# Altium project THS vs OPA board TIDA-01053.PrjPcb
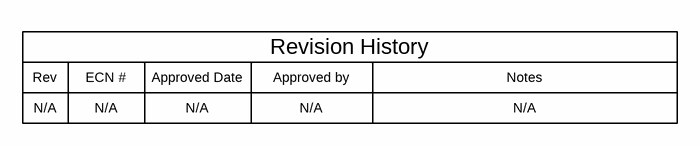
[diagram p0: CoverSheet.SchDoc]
CopyrightYear: 2017; PCB_Layout: Eric Beljaars; PCB_Rev: E1; PRJ_Customer: Public Release; PRJ_Engineer: Taras Dudar; PRJ_Number: TIDA-01053; PRJ_Title: ADC Driver; SCH_Rev: E1; TechSupport: http://www.ti.com/support; TID: 01053
3 sheets, 90 parts. Net scope: global (net labels, ports and power ports of the same name join across sheets).
Board file: PCB.PcbDoc
Sheets:
  CoverSheet.SchDoc
  OPA625_VCA_Disto_Hardware.SchDoc
  THS4551_VCA_Disto_Hardware.SchDoc

## Sheet CoverSheet.SchDoc
size 431 x 279 mm; Date: Not shown in title block; ApprovedBy: Not shown in title block; CheckedBy: Not shown in title block; Author: Not shown in title block; CompanyName: Not shown in title block; Engineer: Not shown in title block; Organization: Not shown in title block; Address1: Not shown in title block; Address2: Not shown in title block; Address3: Not shown in title block; Address4: Not shown in title block; DocumentNumber: 1; Revision: Use project parameter SCH_Rev; SheetNumber: 1; SheetTotal: 3; PageSetup: Record=PageOptions¦CenterHorizontal=True¦CenterVertical=True¦PrintScale=1.00¦XCorrection=1.00¦YCorrection=1.00¦PrintKind=0¦BorderSize=5000000¦LeftOffset=0¦BottomOffset=0¦Orientation=2¦PaperLength=1000¦PaperWidth=1000¦Scale=100¦PaperSource=15¦PrintQuality=600¦MediaType=1¦DitherType=10¦PaperKind=Letter¦PrintScaleMode=1

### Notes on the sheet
- Rev
- N/A
- ECN #
- Approved Date
- Approved by
- Revision History
- Notes

## Sheet OPA625_VCA_Disto_Hardware.SchDoc
size 431 x 279 mm; Date: Not shown in title block; ApprovedBy: Not shown in title block; CheckedBy: Not shown in title block; Author: Not shown in title block; CompanyName: Not shown in title block; Engineer: Not shown in title block; Organization: Not shown in title block; Address1: Not shown in title block; Address2: Not shown in title block; Address3: Not shown in title block; Address4: Not shown in title block; DocumentNumber: 1; Revision: Use project parameter SCH_Rev; SheetNumber: 2; SheetTotal: 3; PageSetup: Record=PageOptions¦CenterHorizontal=True¦CenterVertical=True¦PrintScale=1.00¦XCorrection=1.00¦YCorrection=1.00¦PrintKind=0¦BorderSize=5000000¦LeftOffset=0¦BottomOffset=0¦Orientation=2¦PaperLength=1000¦PaperWidth=1000¦Scale=100¦PaperSource=15¦PrintQuality=600¦MediaType=1¦DitherType=10¦PaperKind=Letter¦PrintScaleMode=1
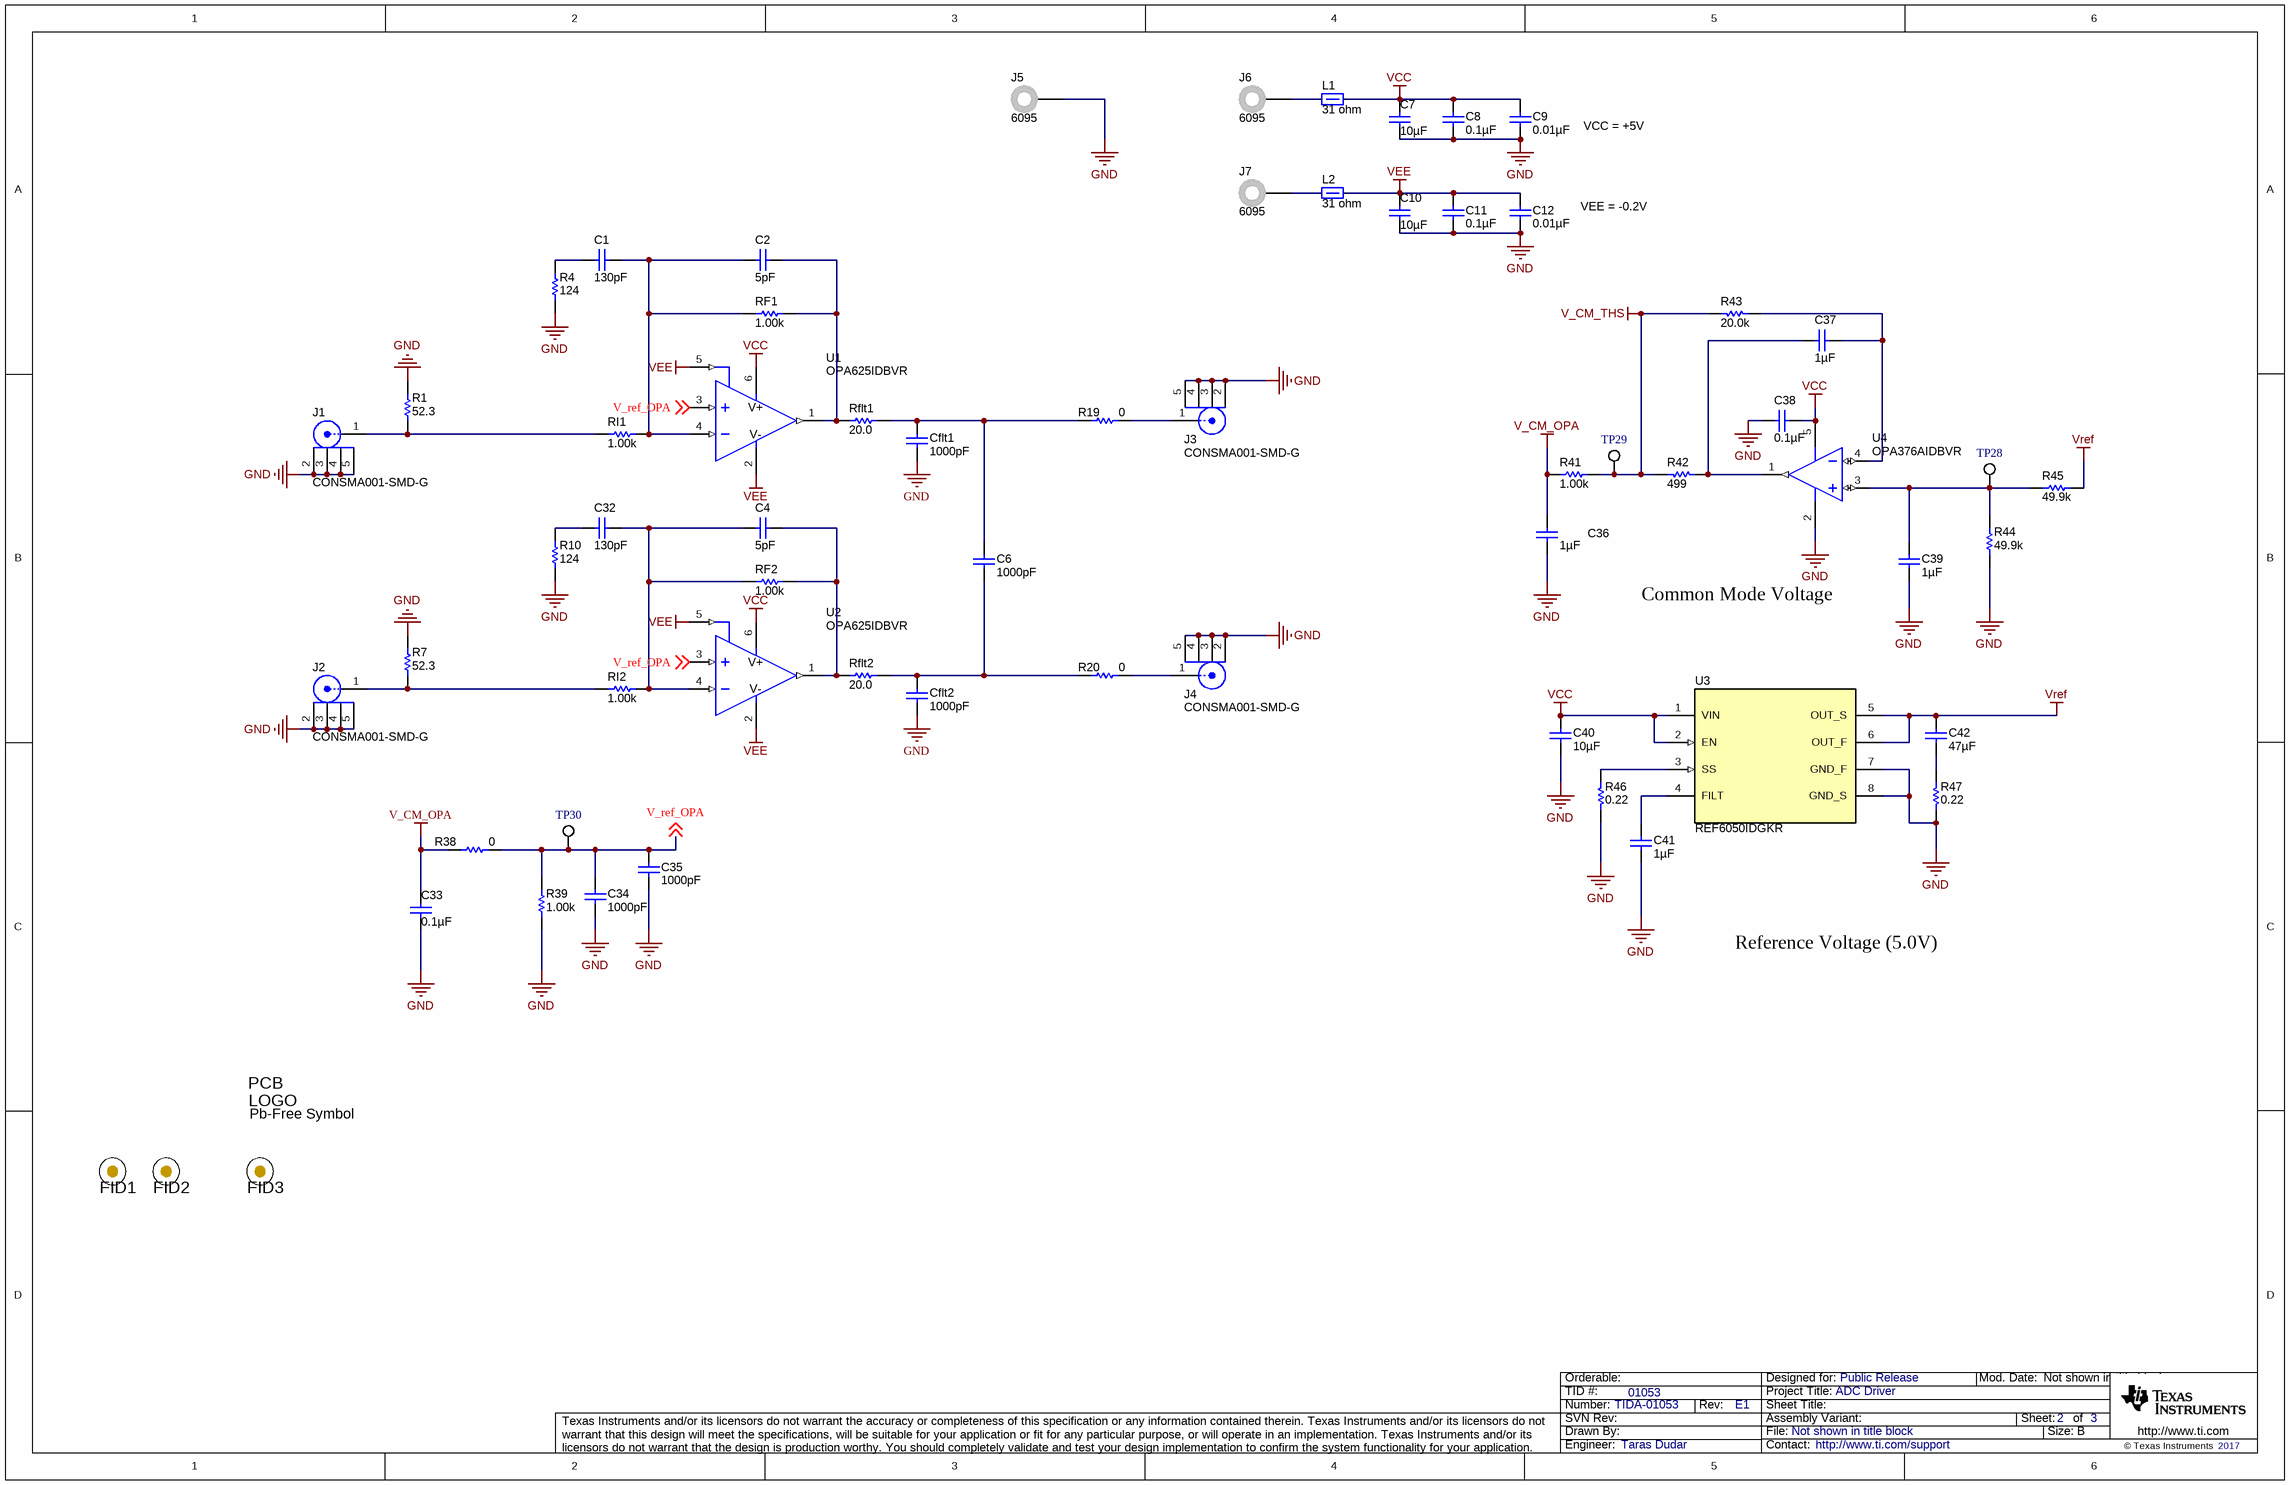
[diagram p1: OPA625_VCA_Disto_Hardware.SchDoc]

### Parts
C1  ValueDisplayed: 130pF  [0603]  (hidden comment: GRM1885C2A131JA01D)
C2  ValueDisplayed: 5pF  [0603]  (hidden comment: GRM1885C2A5R0CA01D)
C4  ValueDisplayed: 5pF  [0603]  (hidden comment: GRM1885C2A5R0CA01D)
C6  ValueDisplayed: 1000pF  [0603]  (hidden comment: C1608C0G2A102J080AA)
C7  ValueDisplayed: 10µF  [1210_280]  (hidden comment: UMK325AB7106KM-T)
C8  ValueDisplayed: 0.1µF  [0603]  (hidden comment: GRM188R72A104KA35D)
C9  ValueDisplayed: 0.01µF  [0603]  (hidden comment: GRM188R71E103KA01D)
C10  ValueDisplayed: 10µF  [1210_280]  (hidden comment: UMK325AB7106KM-T)
C11  ValueDisplayed: 0.1µF  [0603]  (hidden comment: GRM188R72A104KA35D)
C12  ValueDisplayed: 0.01µF  [0603]  (hidden comment: GRM188R71E103KA01D)
C32  ValueDisplayed: 130pF  [0603]  (hidden comment: GRM1885C2A131JA01D)
C33  ValueDisplayed: 0.1µF  [0603]  (hidden comment: C0603C104J3RACTU)
C34  ValueDisplayed: 1000pF  [0603]  (hidden comment: C0603C102J5GAC)
C35  ValueDisplayed: 1000pF  [0603]  (hidden comment: C0603C102J5GAC)
C36  ValueDisplayed: 1µF  [0603]  (hidden comment: GRM188R71E105KA12D)
C37  ValueDisplayed: 1µF  [0603]  (hidden comment: GRM188R71E105KA12D)
C38  ValueDisplayed: 0.1µF  [0603]  (hidden comment: C0603C104J3RACTU)
C39  ValueDisplayed: 1µF  [0603]  (hidden comment: GRM188R71E105KA12D)
C40  ValueDisplayed: 10µF  [0805]  (hidden comment: GRM21BR71A106KE51L)
C41  ValueDisplayed: 1µF  [0603]  (hidden comment: GRM188R71A105KA61D)
C42  ValueDisplayed: 47µF  [1210_270]  (hidden comment: GRM32ER71A476KE15L)
Cflt1  ValueDisplayed: 1000pF  [0603]  (hidden comment: C1608C0G2A102J080AA)
Cflt2  ValueDisplayed: 1000pF  [0603]  (hidden comment: C1608C0G2A102J080AA)
FID1  Fiducial  [Fiducial10-20]  (value not drawn)
FID2  Fiducial  [Fiducial10-20]  (value not drawn)
FID3  Fiducial  [Fiducial10-20]  (value not drawn)
J1  CONSMA001-SMD-G  [Linx_CONSMA001-SMD-G]
J2  CONSMA001-SMD-G  [Linx_CONSMA001-SMD-G]
J3  CONSMA001-SMD-G  [Linx_CONSMA001-SMD-G]
J4  CONSMA001-SMD-G  [Linx_CONSMA001-SMD-G]
J5  6095  [Keystone_6095]
J6  6095  [Keystone_6095]
J7  6095  [Keystone_6095]
L1  value 31 ohm  [1206]  (hidden comment: MI1206K310R-10)
L2  value 31 ohm  [1206]  (hidden comment: MI1206K310R-10)
Logo2  Pb-Free Symbol  [Pb-Free_Overlay_Small]  (no BOM)
R1  ValueDisplayed: 52.3  [0603]  (hidden comment: RC0603FR-0752R3L)
R4  ValueDisplayed: 124  [0603]  (hidden comment: RC0603FR-07124RL)
R7  ValueDisplayed: 52.3  [0603]  (hidden comment: RC0603FR-0752R3L)
R10  ValueDisplayed: 124  [0603]  (hidden comment: RC0603FR-07124RL)
R19  ValueDisplayed: 0  [0402]  (hidden comment: ERJ-2GE0R00X)
R20  ValueDisplayed: 0  [0402]  (hidden comment: ERJ-2GE0R00X)
R38  ValueDisplayed: 0  [0402]  (hidden comment: ERJ-2GE0R00X)
R39  ValueDisplayed: 1.00k  [0603]  (hidden comment: RT0603BRB071KL)
R41  ValueDisplayed: 1.00k  [0603]  (hidden comment: RT0603BRB071KL)
R42  ValueDisplayed: 499  [0603]  (hidden comment: RG1608P-4990-B-T5)
R43  ValueDisplayed: 20.0k  [0603]  (hidden comment: RG1608P-203-B-T5)
R44  ValueDisplayed: 49.9k  [0603]  (hidden comment: RG1608P-4992-B-T5)
R45  ValueDisplayed: 49.9k  [0603]  (hidden comment: RG1608P-4992-B-T5)
R46  value 0.22  [0603]  (hidden comment: ERJ-3RQFR22V)
R47  value 0.22  [0603]  (hidden comment: ERJ-3RQFR22V)
RF1  ValueDisplayed: 1.00k  [0603]  (hidden comment: RT0603BRB071KL)
RF2  ValueDisplayed: 1.00k  [0603]  (hidden comment: RT0603BRB071KL)
Rflt1  ValueDisplayed: 20.0  [0603]  (hidden comment: RT0603BRD0720RL)
Rflt2  ValueDisplayed: 20.0  [0603]  (hidden comment: RT0603BRD0720RL)
RI1  ValueDisplayed: 1.00k  [0603]  (hidden comment: RT0603BRB071KL)
RI2  ValueDisplayed: 1.00k  [0603]  (hidden comment: RT0603BRB071KL)
TP28  5015  [Testpoint_Keystone_Miniature]  (value not drawn)
TP29  5015  [Testpoint_Keystone_Miniature]  (value not drawn)
TP30  5015  [Testpoint_Keystone_Miniature]  (value not drawn)
U1  OPA625IDBVR  [DBV0006A_N]
U2  OPA625IDBVR  [DBV0006A_N]
U3  REF6050IDGKR  [DGK0008A_N]
U4  OPA376AIDBVR  [DBV0005A_N]

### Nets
GND: C7.2 C8.2 C9.2 C10.2 C11.2 C12.2 C33.2 C34.2 C35.2 C36.2 C38.1 C39.2 C40.1 C41.2 Cflt1.2 Cflt2.2 J1.2 J1.3 J1.4 J1.5 J2.2 J2.3 J2.4 J2.5 J3.2 J3.3 J3.4 J3.5 J4.2 J4.3 J4.4 J4.5 J5.1 R1.2 R4.1 R7.2 R10.1 R39.1 R44.1 R46.1 R47.2 U3.7(GND_F) U3.8(GND_S) U4.2(V-)
V_CM_OPA: C33.1 C36.1 R38.1 R41.1
V_CM_THS: R41.2 R42.2 R43.2 TP29.1
VCC: C7.1 C8.1 C9.1 C38.2 C40.2 L1.2 U1.6(V+) U2.6(V+) U3.1(VIN) U3.2(EN) U4.5(V+)
VEE: C10.1 C11.1 C12.1 L2.2 U1.2(V-) U1.5(MODE) U2.2(V-) U2.5(MODE)
Vref: C42.1 R45.2 U3.5(OUT_S) U3.6(OUT_F)
V_ref_OPA: C34.1 C35.1 R38.2 R39.2 TP30.1 U1.3(IN+) U2.3(IN+) ; off-sheet V_ref_OPA
NetC1_1: C1.1 R4.2
NetC1_2: C1.2 C2.2 RF1.1 RI1.2 U1.4(IN-)
NetC2_1: C2.1 RF1.2 Rflt1.1 U1.1(OUT)
NetC4_1: C4.1 RF2.2 Rflt2.1 U2.1(OUT)
NetC4_2: C4.2 C32.2 RF2.1 RI2.2 U2.4(IN-)
NetC6_1: C6.1 Cflt1.1 R19.1 Rflt1.2
NetC6_2: C6.2 Cflt2.1 R20.1 Rflt2.2
NetC32_1: C32.1 R10.2
NetC37_1: C37.1 R42.1 U4.1(OUT)
NetC37_2: C37.2 R43.1 U4.4(IN-)
NetC39_1: C39.1 R44.2 R45.1 TP28.1 U4.3(IN+)
NetC41_1: C41.1 U3.4(FILT)
NetC42_2: C42.2 R47.1
NetJ1_1: J1.1 R1.1 RI1.1
NetJ2_1: J2.1 R7.1 RI2.1
NetJ3_1: J3.1 R19.2
NetJ4_1: J4.1 R20.2
NetJ6_1: J6.1 L1.1
NetJ7_1: J7.1 L2.1
NetR46_2: R46.2 U3.3(SS)

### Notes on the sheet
- VCC = +5V
- VEE = -0.2V
- Common Mode Voltage
- Reference Voltage (5.0V)

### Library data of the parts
C1 C32 = GRM1885C2A131JA01D: CAP, CERM, 130 pF, 100 V, +/- 5%, C0G/NP0, 0603; Manufacturer: MuRata; Polarized: N; CompType: Capacitor; Value: 130pF; U/M: EA; Cap_F: 0.00000000013; Tolerance_%: 5; Value1: Unknown; VDC_V: 100; Value2: 100V; TaMin_C: -55; TaMax_C: 125; SizeArea_mm2: 1.28; SizeAreaWB_mm2: 4.68; SizeX_mm: 1.6; SizeY_mm: 0.8; SizeZ_mm: 1; AEC Category: Q200
C2 C4 = GRM1885C2A5R0CA01D: CAP, CERM, 5 pF, 100 V, +/- 5%, C0G/NP0, 0603; Manufacturer: MuRata; Polarized: N; CompType: Capacitor; Value: 5pF; U/M: EA; Cap_F: 0.000000000005; Tolerance_%: 5; Value1: Unknown; VDC_V: 100; Value2: 100V; TaMin_C: -55; TaMax_C: 125; SizeArea_mm2: 1.28; SizeAreaWB_mm2: 4.68; SizeX_mm: 1.6; SizeY_mm: 0.8; SizeZ_mm: 1; AEC Category: Q200
C6 Cflt1 Cflt2 = C1608C0G2A102J080AA: CAP, CERM, 1000 pF, 100 V, +/- 5%, C0G/NP0, 0603; Manufacturer: TDK; Polarized: N; CompType: Capacitor; Value: 1000pF; U/M: EA; Cap_F: 0.000000001; Tolerance_%: 5; ESR_ohm: 0.0589; Value1: 0.0589 ohm; VDC_V: 100; Value2: 100V; TaMin_C: -55; TaMax_C: 125; SizeArea_mm2: 1.28; SizeAreaWB_mm2: 4.68; SizeX_mm: 1.6; SizeY_mm: 0.8; SizeZ_mm: 1; AEC Category: Q200
C7 C10 = UMK325AB7106KM-T: CAP, CERM, 10 µF, 50 V, +/- 10%, X7R, 1210; Manufacturer: Taiyo Yuden; Polarized: N; CompType: Capacitor; Value: 10uF; U/M: EA; Cap_F: 0.00001; Tolerance_%: 10; Value1: Unknown; VDC_V: 50; Value2: 50V; TaMin_C: -55; TaMax_C: 125; Cap_Case: 1210; AEC Category: Q200
C8 C11 = GRM188R72A104KA35D: CAP, CERM, 0.1 µF, 100 V, +/- 10%, X7R, 0603; Manufacturer: MuRata; Polarized: N; CompType: Capacitor; Value: 0.1uF; U/M: EA; Cap_F: 0.0000001; Tolerance_%: 10; Value1: Unknown; VDC_V: 100; Value2: 100V; TaMin_C: -55; TaMax_C: 125; SizeArea_mm2: 1.28; SizeAreaWB_mm2: 4.68; SizeX_mm: 1.6; SizeY_mm: 0.8; SizeZ_mm: 1; AEC Category: Q200
C9 C12 = GRM188R71E103KA01D: CAP, CERM, 0.01 µF, 25 V, +/- 10%, X7R, 0603; Manufacturer: MuRata; Polarized: N; CompType: Capacitor; Value: 0.01uF; U/M: EA; Cap_F: 0.00000001; Tolerance_%: 10; Value1: Unknown; VDC_V: 25; Value2: 25V; TaMin_C: -55; TaMax_C: 125; SizeArea_mm2: 1.28; SizeAreaWB_mm2: 4.68; SizeX_mm: 1.6; SizeY_mm: 0.8; SizeZ_mm: 1; AEC Category: Q200
C33 = C0603C104J3RACTU: CAP, CERM, 0.1 µF, 25 V, +/- 5%, X7R, 0603; Manufacturer: Kemet; Polarized: N; CompType: Capacitor; Value: 0.1uF; U/M: EA; Cap_F: 0.0000001; Tolerance_%: 5; Value1: Unknown; VDC_V: 25; Value2: 25V; TaMin_C: -55; TaMax_C: 125
C34 C35 = C0603C102J5GAC: CAP, CERM, 1000 pF, 50 V, +/- 5%, C0G/NP0, 0603; Manufacturer: Kemet; Polarized: N; CompType: Capacitor; Value: 1000pF; U/M: EA; Cap_F: 0.000000001; Tolerance_%: 5; Value1: Unknown; VDC_V: 50; Value2: 50V; TaMin_C: -55; TaMax_C: 125; SizeArea_mm2: 1.28; SizeAreaWB_mm2: 4.68; SizeX_mm: 1.6; SizeY_mm: 0.8; SizeZ_mm: 1; AEC Category: Q200
C36 C37 C39 = GRM188R71E105KA12D: CAP, CERM, 1 µF, 25 V, +/- 10%, X7R, 0603; Manufacturer: MuRata; Polarized: N; CompType: Capacitor; Value: 1uF; U/M: EA; Cap_F: 0.000001; Tolerance_%: 10; Value1: Unknown; VDC_V: 25; Value2: 25V; TaMin_C: -55; TaMax_C: 125; AEC Category: Q200
C38 = C0603C104J3RACTU: CAP, CERM, 0.1 µF, 25 V, +/- 5%, X7R, 0603; Manufacturer: Kemet; Polarized: N; CompType: Capacitor; Value: 0.1uF; U/M: EA; Cap_F: 0.0000001; Tolerance_%: 5; Value1: Unknown; VDC_V: 25; Value2: 25V; TaMin_C: -55; TaMax_C: 125; AEC Category: Q200
C40 = GRM21BR71A106KE51L: CAP, CERM, 10uF, 10V, +/-10%, X7R, 0805; Manufacturer: MuRata; Polarized: N; CompType: Capacitor; U/M: EA; Cap_F: 0.00001; Tolerance_%: 10; ESR_Ohm: 0.003; Value1: 0.003 ohm; TaMin_C: -55; TaMax_C: 125
C41 = GRM188R71A105KA61D: CAP, CERM, 1uF, 10V, +/-10%, X7R, 0603; Manufacturer: MuRata; Polarized: N; CompType: Capacitor; U/M: EA; Cap_F: 0.000001; Tolerance_%: 10; ESR_Ohm: 0.011; Value1: 0.011 ohm; TaMin_C: -55; TaMax_C: 125
C42 = GRM32ER71A476KE15L: CAP, CERM, 47 µF, 10 V, +/- 10%, X7R, 1210; Manufacturer: MuRata; Polarized: N; CompType: Capacitor; Value: 47uF; U/M: EA; Cap_F: 0.000047; Tolerance_%: 10; Value1: Unknown; Value2: 10V; TaMin_C: -55; TaMax_C: 125; Cap_Case: 1210; SizeArea_mm2: 8; SizeAreaWB_mm2: 14.7; SizeX_mm: 3.2; SizeY_mm: 2.5; SizeZ_mm: 2.7; AEC Category: Q200
FID1-FID3 = Fiducial: Fiducial mark.  There is nothing to buy or mount.; SymbolCreator: codlsc
J1-J4 = CONSMA001-SMD-G: Jack, SMA, PCB, Gold, SMT; Manufacturer: Linx Technologies; SymbolCreator: X0208326
J5-J7 = 6095: Standard Banana Jack, Uninsulated; Manufacturer: Keystone; SymbolCreator: a0412235; CompType: Connector
L1 L2 = MI1206K310R-10: Ferrite Bead, 31 ohm @ 100 MHz, 1.5 A, 1206; Manufacturer: Laird-Signal Integrity Products; Imax_A: 1.5; DCR_ohm: 0.045; Value1: 0.045 ohm; Value2: 1.5A; ZTyp@100MHz_Ohm: 31; Ztyp@1GHz_Ohm: 41
Logo2 = Pb-Free: SymbolCreator: a0412235
R1 R7 = RC0603FR-0752R3L: RES, 52.3, 1%, 0.1 W, 0603; Manufacturer: Yageo America; CompType: Resistor; Value: 52.3; Value_Code: 52R3; Tolerance_%: 1; Power_W: 0.1; Value2: 0.1W; VDC_V: 150; TempCo: 200 ppm/C; SizeArea_mm2: 1.28; SizeX_mm: 1.6; SizeY_mm: 0.8; EIA_Code: E96; U/M: EA; AEC Category: Q200
R4 R10 = RC0603FR-07124RL: RES, 124, 1%, 0.1 W, 0603; Manufacturer: Yageo America; CompType: Resistor; Value: 124; Value_Code: 124R; Tolerance_%: 1; Power_W: 0.1; Value2: 0.1W; VDC_V: 150; TempCo: 200 ppm/C; SizeArea_mm2: 1.28; SizeX_mm: 1.6; SizeY_mm: 0.8; EIA_Code: E96; U/M: EA; AEC Category: Q200
R19 R20 R38 = ERJ-2GE0R00X: RES, 0, 5%, 0.063 W, 0402; Manufacturer: Panasonic; CompType: Resistor; Value: 0; Value_Code: 0000; Tolerance_%: 5; Power_W: 0.063; Value2: 0.063W; VDC_V: 50; TempCo: 600 ppm/C; EIA_Code: E24; U/M: EA; AEC Category: Q200
R39 R41 RF1 RF2 RI1 RI2 = RT0603BRB071KL: RES, 1.00 k, 0.1%, 0.1 W, 0603; Manufacturer: Yageo America; CompType: Resistor; Value: 1.00k; Res_ohm: 1000; Value_Code: 1k00; Tolerance_%: 0.1; Value2: 0.1W; VDC_V: 75; TempCo: 10 ppm/C; SizeArea_mm2: 1.28; SizeX_mm: 1.6; SizeY_mm: 0.8; SizeZ_mm: 1; EIA_Code: E192; U/M: EA; AEC Category: Q200; AEC Qualified: N
R42 = RG1608P-4990-B-T5: RES, 499, 0.1%, 0.1 W, 0603; Manufacturer: Susumu Co Ltd; CompType: Resistor; Value: 499; Value_Code: 499R; Tolerance_%: 0.1; Value2: 0.1W; VDC_V: 75; TempCo: 25 ppm/C; EIA_Code: E192; U/M: EA; AEC Category: Q200
R43 = RG1608P-203-B-T5: RES, 20.0 k, 0.1%, 0.1 W, 0603; Manufacturer: Susumu Co Ltd; CompType: Resistor; Value: 20.0k; Res_ohm: 20000; Value_Code: 20k0; Tolerance_%: 0.1; Value2: 0.1W; VDC_V: 75; TempCo: 25 ppm/C; EIA_Code: E192; U/M: EA; AEC Category: Q200
R44 R45 = RG1608P-4992-B-T5: RES, 49.9 k, 0.1%, 0.1 W, 0603; Manufacturer: Susumu Co Ltd; CompType: Resistor; Value: 49.9k; Res_ohm: 49900; Value_Code: 49k9; Tolerance_%: 0.1; Value2: 0.1W; VDC_V: 75; TempCo: 25 ppm/C; EIA_Code: E192; U/M: EA; AEC Category: Q200
R46 R47 = ERJ-3RQFR22V: RES, 0.22 ohm, 1%, 0.1W, 0603; Manufacturer: Panasonic; CompType: Resistor; Value_Code: R220; Tolerance_%: 1; Power_W: 0.1; TempCo: 300 ppm/C; EIA_Code: E96; U/M: EA
Rflt1 Rflt2 = RT0603BRD0720RL: RES, 20.0, 0.1%, 0.1 W, 0603; Manufacturer: Yageo America; CompType: Resistor; Value: 20.0; Res_ohm: 20; Value_Code: 20R0; Tolerance_%: 0.1; Value2: 0.1W; VDC_V: 75; TempCo: 25 ppm/C; SizeArea_mm2: 1.28; SizeX_mm: 1.6; SizeY_mm: 0.8; SizeZ_mm: 1; EIA_Code: E192; U/M: EA; AEC Category: Q200
TP28-TP30 = 5015: Test Point, Miniature, SMT; Manufacturer: Keystone; CompType: Test Point Loop
U1 U2 = OPA625IDBVR: High Bandwidth, High Precision, Low Noise and Distortion Amplifier with Ultra-Fast Transition time Low Power mode, DBV0006A (SOT-6); Alternate PartNumber: OPA625IDBVT; Manufacturer: Texas Instruments; SymbolCreator: Altium; SizeArea_mm2: 8.12; SizeAreaWB_mm2: 14.82; SizeX_mm: 2.8; SizeY_mm: 2.9; SizeZ_mm: 1.45; CompType: IC; U/M: EA
U3 = REF6050IDGKR: High-Precision Voltage Reference with Integrated High-Bandwidth Buffer, DGK0008A (VSSOP-8); Alternate PartNumber: REF6050IDGKT; Manufacturer: Texas Instruments; SymbolCreator: Altium; SizeArea_mm2: 15.655; SizeAreaWB_mm2: 35.955; SizeX_mm: 5.05; SizeY_mm: 3.1; SizeZ_mm: 1.1; CompType: IC; U/M: EA
U4 = OPA376AIDBVR: Precision, Low Noise, Low Iq Operational Amplifier, 2.2 to 5.5 V, -40 to 125 degC, 5-pin SOT23 (DBV0005A), Green (RoHS & no Sb/Br); Manufacturer: Texas Instruments; Alternate PartNumber: Equivalent; CMRR(Min)(dB): 76; IIB(Max)(pA): 10; Iq per channel(Max)(mA): 0.95; Number of Channels: 1; Offset Drift(Typ)(uV/C): 0.32; Slew Rate(Typ)(V/us): 2; Sub Family: Low Input Bias Current Amp (<=10pA), Low Noise Amp (<=10nV/rtHz), Low Offset Voltage Amplifier (<=500uV), Low Supply Voltage Amplifier (<=2.7V), Precision Amplifier; Total Supply Voltage(Max)(+5V is 5, +/-5V is 10): 5.5; Total Supply Voltage(Min)(+5V is 5, +/-5V is 10): 2.2; Vio (25C)(Max)(mV): 0.025; Vn at 1kHz(Typ)(nV/rtHz): 7.5

## Sheet THS4551_VCA_Disto_Hardware.SchDoc
size 431 x 279 mm; Date: Not shown in title block; ApprovedBy: Not shown in title block; CheckedBy: Not shown in title block; Author: Not shown in title block; CompanyName: Not shown in title block; Engineer: Not shown in title block; Organization: Not shown in title block; Address1: Not shown in title block; Address2: Not shown in title block; Address3: Not shown in title block; Address4: Not shown in title block; DocumentNumber: 1; Revision: Use project parameter SCH_Rev; SheetNumber: 2; SheetTotal: 3; PageSetup: Record=PageOptions¦CenterHorizontal=True¦CenterVertical=True¦PrintScale=1.00¦XCorrection=1.00¦YCorrection=1.00¦PrintKind=0¦BorderSize=5000000¦LeftOffset=0¦BottomOffset=0¦Orientation=2¦PaperLength=1000¦PaperWidth=1000¦Scale=100¦PaperSource=15¦PrintQuality=600¦MediaType=1¦DitherType=10¦PaperKind=Letter¦PrintScaleMode=1
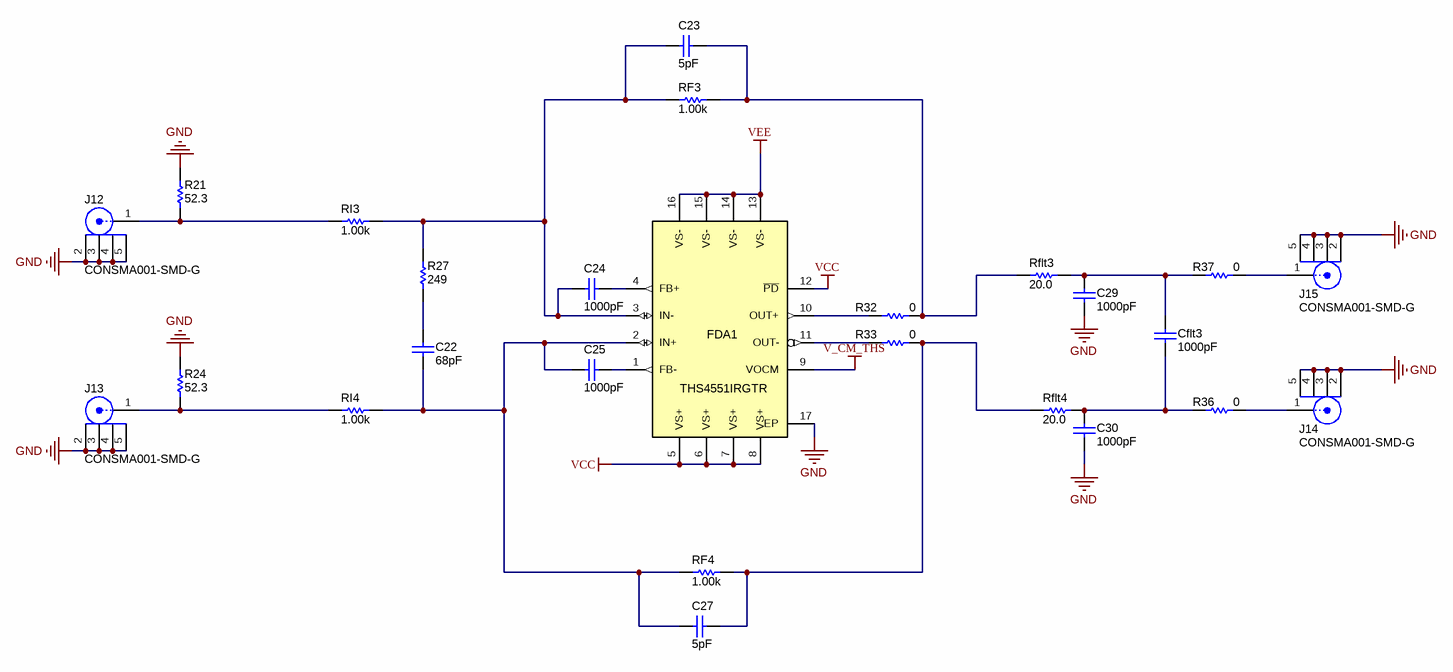
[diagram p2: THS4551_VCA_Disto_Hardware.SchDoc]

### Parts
C22  ValueDisplayed: 68pF  [0603]  (hidden comment: GRM1885C2A680JA01D)
C23  ValueDisplayed: 5pF  [0603]  (hidden comment: GRM1885C2A5R0CA01D)
C24  ValueDisplayed: 1000pF  [0603]  (hidden comment: C1608C0G2A102J080AA)
C25  ValueDisplayed: 1000pF  [0603]  (hidden comment: C1608C0G2A102J080AA)
C27  ValueDisplayed: 5pF  [0603]  (hidden comment: GRM1885C2A5R0CA01D)
C29  ValueDisplayed: 1000pF  [0603]  (hidden comment: C1608C0G2A102J080AA)
C30  ValueDisplayed: 1000pF  [0603]  (hidden comment: C1608C0G2A102J080AA)
Cflt3  ValueDisplayed: 1000pF  [0603]  (hidden comment: C1608C0G2A102J080AA)
FDA1  THS4551IRGTR  [RGT0016A]
J12  CONSMA001-SMD-G  [Linx_CONSMA001-SMD-G]
J13  CONSMA001-SMD-G  [Linx_CONSMA001-SMD-G]
J14  CONSMA001-SMD-G  [Linx_CONSMA001-SMD-G]
J15  CONSMA001-SMD-G  [Linx_CONSMA001-SMD-G]
R21  ValueDisplayed: 52.3  [0603]  (hidden comment: RC0603FR-0752R3L)
R24  ValueDisplayed: 52.3  [0603]  (hidden comment: RC0603FR-0752R3L)
R27  ValueDisplayed: 249  [0603]  (hidden comment: CRCW0603249RFKEA)
R32  ValueDisplayed: 0  [0402]  (hidden comment: ERJ-2GE0R00X)
R33  ValueDisplayed: 0  [0402]  (hidden comment: ERJ-2GE0R00X)
R36  ValueDisplayed: 0  [0402]  (hidden comment: ERJ-2GE0R00X)
R37  ValueDisplayed: 0  [0402]  (hidden comment: ERJ-2GE0R00X)
RF3  ValueDisplayed: 1.00k  [0603]  (hidden comment: RT0603BRB071KL)
RF4  ValueDisplayed: 1.00k  [0603]  (hidden comment: RT0603BRB071KL)
Rflt3  ValueDisplayed: 20.0  [0603]  (hidden comment: RT0603BRD0720RL)
Rflt4  ValueDisplayed: 20.0  [0603]  (hidden comment: RT0603BRD0720RL)
RI3  ValueDisplayed: 1.00k  [0603]  (hidden comment: RT0603BRB071KL)
RI4  ValueDisplayed: 1.00k  [0603]  (hidden comment: RT0603BRB071KL)

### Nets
GND: C29.2 C30.2 FDA1.17(EP) J12.2 J12.3 J12.4 J12.5 J13.2 J13.3 J13.4 J13.5 J14.2 J14.3 J14.4 J14.5 J15.2 J15.3 J15.4 J15.5 R21.2 R24.2
V_CM_THS: FDA1.9(VOCM)
VCC: FDA1.5(VS+) FDA1.6(VS+) FDA1.7(VS+) FDA1.8(VS+) FDA1.12(~{PD})
VEE: FDA1.13(VS-) FDA1.14(VS-) FDA1.15(VS-) FDA1.16(VS-)
NetC22_1: C22.1 R27.1
NetC22_2: C22.2 C25.2 C27.2 FDA1.2(IN+) RF4.1 RI4.2
NetC23_1: C23.1 R32.2 RF3.2 Rflt3.1
NetC23_2: C23.2 C24.2 FDA1.3(IN-) R27.2 RF3.1 RI3.2
NetC24_1: C24.1 FDA1.4(FB+)
NetC25_1: C25.1 FDA1.1(FB-)
NetC27_1: C27.1 R33.2 RF4.2 Rflt4.1
NetC29_1: C29.1 Cflt3.1 R37.1 Rflt3.2
NetC30_1: C30.1 Cflt3.2 R36.1 Rflt4.2
NetFDA1_10: FDA1.10(OUT+) R32.1
NetFDA1_11: FDA1.11(OUT-) R33.1
NetJ12_1: J12.1 R21.1 RI3.1
NetJ13_1: J13.1 R24.1 RI4.1
NetJ14_1: J14.1 R36.2
NetJ15_1: J15.1 R37.2

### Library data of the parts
C22 = GRM1885C2A680JA01D: CAP, CERM, 68 pF, 100 V, +/- 5%, C0G/NP0, 0603; Manufacturer: MuRata; Polarized: N; CompType: Capacitor; Value: 68pF; U/M: EA; Cap_F: 0.000000000068; Tolerance_%: 5; Value1: Unknown; VDC_V: 100; Value2: 100V; TaMin_C: -55; TaMax_C: 125; SizeArea_mm2: 1.28; SizeAreaWB_mm2: 4.68; SizeX_mm: 1.6; SizeY_mm: 0.8; SizeZ_mm: 1; AEC Category: Q200
C23 C27 = GRM1885C2A5R0CA01D: as C2 on sheet OPA625_VCA_Disto_Hardware
C24 C25 C29 C30 Cflt3 = C1608C0G2A102J080AA: as C6 on sheet OPA625_VCA_Disto_Hardware
FDA1 = THS4551IRGTR: Low Power, Precision, 160MHz, Fully Differential Amplifier, RGT0016A; Alternate PartNumber: THS4551IRGTT; Manufacturer: Texas Instruments; SymbolCreator: Altium; SizeX_mm: 4; SizeZ_mm: 1; CompType: IC; U/M: EA
J12-J15 = CONSMA001-SMD-G: as J1 on sheet OPA625_VCA_Disto_Hardware
R21 R24 = RC0603FR-0752R3L: as R1 on sheet OPA625_VCA_Disto_Hardware
R27 = CRCW0603249RFKEA: RES, 249, 1%, 0.1 W, 0603; Manufacturer: Vishay-Dale; CompType: Resistor; Value: 249; Value_Code: 249R; Tolerance_%: 1; Power_W: 0.1; Value2: 0.1W; VDC_V: 75; TempCo: 100 ppm/C; SizeArea_mm2: 1.28; SizeX_mm: 1.6; SizeY_mm: 0.8; EIA_Code: E96; U/M: EA; AEC Category: Q200
R32 R33 R36 R37 = ERJ-2GE0R00X: as R19 on sheet OPA625_VCA_Disto_Hardware
RF3 RF4 RI3 RI4 = RT0603BRB071KL: as R39 on sheet OPA625_VCA_Disto_Hardware
Rflt3 Rflt4 = RT0603BRD0720RL: as Rflt1 on sheet OPA625_VCA_Disto_Hardware

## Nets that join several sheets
GND: OPA625_VCA_Disto_Hardware (44 pins), THS4551_VCA_Disto_Hardware (21 pins)
V_CM_THS: OPA625_VCA_Disto_Hardware (R41.2 R42.2 R43.2 TP29.1), THS4551_VCA_Disto_Hardware (FDA1.9)
VCC: OPA625_VCA_Disto_Hardware (11 pins), THS4551_VCA_Disto_Hardware (5 pins)
VEE: OPA625_VCA_Disto_Hardware (8 pins), THS4551_VCA_Disto_Hardware (FDA1.13 FDA1.14 FDA1.15 FDA1.16)

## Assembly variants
001: not fitted C1 C6 C22 C24 C25 C29 C30 C32 FID1 FID2 FID3 R4 R10 R27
